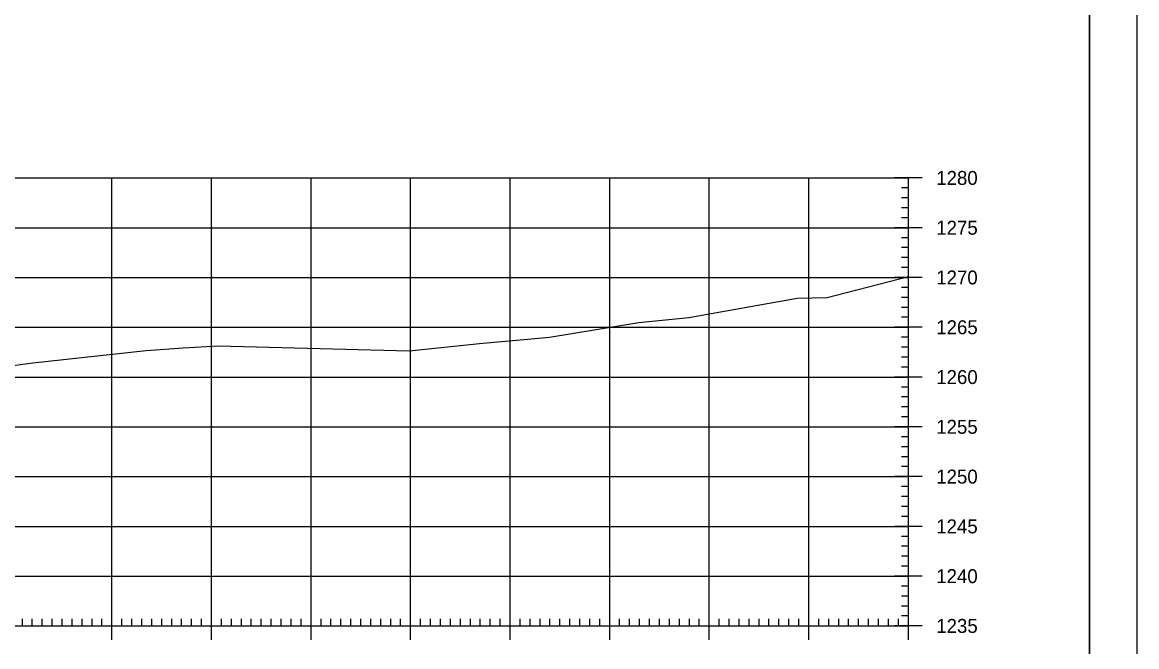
# Model space of a CAD drawing. Extents: x 1406028 to 1412453, y 321733 to 325986.
# Drawn here: x 1409105.8 to 1409217.7, y 322357.5 to 322420.2 of the extents above; entities that cross this region are included whole.
import ezdxf

# ---------------------------------------------------------------- set-up
doc = ezdxf.new("R2010")
doc.units = 0
for name, color, linetype in [('R_Axis', 7, 'Continuous'), ('R_Axis Annot', 7, 'Continuous'), ('R_Border', 7, 'Continuous'), ('R_Exist Surface', 7, 'Continuous'), ('R_Grid', 7, 'Continuous'), ('R_No Plot', 7, 'Continuous')]:
    doc.layers.add(name, color=color, linetype=linetype)

msp = doc.modelspace()

# ---------------------------------------------------------------- linework, layer by layer
at = {"layer": 'R_Axis'}
for p, q in [((1409196.21, 322404.55), (1409193.41, 322404.55)), ((1409194.81, 322359.55), (1409194.81, 322404.55)), ((1409194.81, 322403.55), (1409194.11, 322403.55)), ((1409194.81, 322402.55), (1409194.11, 322402.55)), ((1409194.81, 322401.55), (1409194.11, 322401.55)), ((1409194.81, 322400.55), (1409194.11, 322400.55)), ((1409196.21, 322399.55), (1409193.41, 322399.55)), ((1409194.81, 322398.55), (1409194.11, 322398.55)), ((1409194.81, 322397.55), (1409194.11, 322397.55)), ((1409194.81, 322396.55), (1409194.11, 322396.55)), ((1409194.81, 322395.55), (1409194.11, 322395.55)), ((1409196.21, 322394.55), (1409193.41, 322394.55)), ((1409194.81, 322393.55), (1409194.11, 322393.55)), ((1409194.81, 322392.55), (1409194.11, 322392.55)), ((1409194.81, 322391.55), (1409194.11, 322391.55)), ((1409194.81, 322390.55), (1409194.11, 322390.55)), ((1409196.21, 322389.55), (1409193.41, 322389.55)), ((1409194.81, 322388.55), (1409194.11, 322388.55)), ((1409194.81, 322387.55), (1409194.11, 322387.55)), ((1409194.81, 322386.55), (1409194.11, 322386.55)), ((1409194.81, 322385.55), (1409194.11, 322385.55)), ((1409196.21, 322384.55), (1409193.41, 322384.55)), ((1409194.81, 322383.55), (1409194.11, 322383.55)), ((1409194.81, 322382.55), (1409194.11, 322382.55)), ((1409194.81, 322381.55), (1409194.11, 322381.55)), ((1409194.81, 322380.55), (1409194.11, 322380.55)), ((1409196.21, 322379.55), (1409193.41, 322379.55)), ((1409194.81, 322378.55), (1409194.11, 322378.55)), ((1409194.81, 322377.55), (1409194.11, 322377.55)), ((1409194.81, 322376.55), (1409194.11, 322376.55)), ((1409194.81, 322375.55), (1409194.11, 322375.55)), ((1409196.21, 322374.55), (1409193.41, 322374.55)), ((1409194.81, 322373.55), (1409194.11, 322373.55)), ((1409194.81, 322372.55), (1409194.11, 322372.55)), ((1409194.81, 322371.55), (1409194.11, 322371.55)), ((1409194.81, 322370.55), (1409194.11, 322370.55)), ((1409196.21, 322369.55), (1409193.41, 322369.55)), ((1409194.81, 322368.55), (1409194.11, 322368.55)), ((1409194.81, 322367.55), (1409194.11, 322367.55)), ((1409194.81, 322366.55), (1409194.11, 322366.55)), ((1409194.81, 322365.55), (1409194.11, 322365.55)), ((1409196.21, 322364.55), (1409193.41, 322364.55)), ((1409194.81, 322363.55), (1409194.11, 322363.55)), ((1409194.81, 322362.55), (1409194.11, 322362.55)), ((1409114.81, 322358.15), (1409114.81, 322360.95)), ((1409124.81, 322358.15), (1409124.81, 322360.95)), ((1409134.81, 322358.15), (1409134.81, 322360.95)), ((1409144.81, 322358.15), (1409144.81, 322360.95)), ((1409154.81, 322358.15), (1409154.81, 322360.95)), ((1409164.81, 322358.15), (1409164.81, 322360.95)), ((1409174.81, 322358.15), (1409174.81, 322360.95)), ((1409184.81, 322358.15), (1409184.81, 322360.95)), ((1409194.81, 322361.55), (1409194.11, 322361.55)), ((1409194.81, 322358.15), (1409194.81, 322360.95)), ((1408914.81, 322359.55), (1409194.81, 322359.55)), ((1409105.81, 322359.55), (1409105.81, 322360.25)), ((1409106.81, 322359.55), (1409106.81, 322360.25)), ((1409107.81, 322359.55), (1409107.81, 322360.25)), ((1409108.81, 322359.55), (1409108.81, 322360.25)), ((1409109.81, 322359.55), (1409109.81, 322360.25)), ((1409110.81, 322359.55), (1409110.81, 322360.25)), ((1409111.81, 322359.55), (1409111.81, 322360.25)), ((1409112.81, 322359.55), (1409112.81, 322360.25)), ((1409113.81, 322359.55), (1409113.81, 322360.25)), ((1409115.81, 322359.55), (1409115.81, 322360.25)), ((1409116.81, 322359.55), (1409116.81, 322360.25)), ((1409117.81, 322359.55), (1409117.81, 322360.25)), ((1409118.81, 322359.55), (1409118.81, 322360.25)), ((1409119.81, 322359.55), (1409119.81, 322360.25)), ((1409120.81, 322359.55), (1409120.81, 322360.25)), ((1409121.81, 322359.55), (1409121.81, 322360.25)), ((1409122.81, 322359.55), (1409122.81, 322360.25)), ((1409123.81, 322359.55), (1409123.81, 322360.25)), ((1409125.81, 322359.55), (1409125.81, 322360.25)), ((1409126.81, 322359.55), (1409126.81, 322360.25)), ((1409127.81, 322359.55), (1409127.81, 322360.25)), ((1409128.81, 322359.55), (1409128.81, 322360.25)), ((1409129.81, 322359.55), (1409129.81, 322360.25)), ((1409130.81, 322359.55), (1409130.81, 322360.25)), ((1409131.81, 322359.55), (1409131.81, 322360.25)), ((1409132.81, 322359.55), (1409132.81, 322360.25)), ((1409133.81, 322359.55), (1409133.81, 322360.25)), ((1409135.81, 322359.55), (1409135.81, 322360.25)), ((1409136.81, 322359.55), (1409136.81, 322360.25)), ((1409137.81, 322359.55), (1409137.81, 322360.25)), ((1409138.81, 322359.55), (1409138.81, 322360.25)), ((1409139.81, 322359.55), (1409139.81, 322360.25)), ((1409140.81, 322359.55), (1409140.81, 322360.25)), ((1409141.81, 322359.55), (1409141.81, 322360.25)), ((1409142.81, 322359.55), (1409142.81, 322360.25)), ((1409143.81, 322359.55), (1409143.81, 322360.25)), ((1409145.81, 322359.55), (1409145.81, 322360.25)), ((1409146.81, 322359.55), (1409146.81, 322360.25)), ((1409147.81, 322359.55), (1409147.81, 322360.25)), ((1409148.81, 322359.55), (1409148.81, 322360.25)), ((1409149.81, 322359.55), (1409149.81, 322360.25)), ((1409150.81, 322359.55), (1409150.81, 322360.25)), ((1409151.81, 322359.55), (1409151.81, 322360.25)), ((1409152.81, 322359.55), (1409152.81, 322360.25)), ((1409153.81, 322359.55), (1409153.81, 322360.25)), ((1409155.81, 322359.55), (1409155.81, 322360.25)), ((1409156.81, 322359.55), (1409156.81, 322360.25)), ((1409157.81, 322359.55), (1409157.81, 322360.25)), ((1409158.81, 322359.55), (1409158.81, 322360.25)), ((1409159.81, 322359.55), (1409159.81, 322360.25)), ((1409160.81, 322359.55), (1409160.81, 322360.25)), ((1409161.81, 322359.55), (1409161.81, 322360.25)), ((1409162.81, 322359.55), (1409162.81, 322360.25)), ((1409163.81, 322359.55), (1409163.81, 322360.25)), ((1409165.81, 322359.55), (1409165.81, 322360.25)), ((1409166.81, 322359.55), (1409166.81, 322360.25)), ((1409167.81, 322359.55), (1409167.81, 322360.25)), ((1409168.81, 322359.55), (1409168.81, 322360.25)), ((1409169.81, 322359.55), (1409169.81, 322360.25)), ((1409170.81, 322359.55), (1409170.81, 322360.25)), ((1409171.81, 322359.55), (1409171.81, 322360.25)), ((1409172.81, 322359.55), (1409172.81, 322360.25)), ((1409173.81, 322359.55), (1409173.81, 322360.25)), ((1409175.81, 322359.55), (1409175.81, 322360.25)), ((1409176.81, 322359.55), (1409176.81, 322360.25)), ((1409177.81, 322359.55), (1409177.81, 322360.25)), ((1409178.81, 322359.55), (1409178.81, 322360.25)), ((1409179.81, 322359.55), (1409179.81, 322360.25)), ((1409180.81, 322359.55), (1409180.81, 322360.25)), ((1409181.81, 322359.55), (1409181.81, 322360.25)), ((1409182.81, 322359.55), (1409182.81, 322360.25)), ((1409183.81, 322359.55), (1409183.81, 322360.25)), ((1409185.81, 322359.55), (1409185.81, 322360.25)), ((1409186.81, 322359.55), (1409186.81, 322360.25)), ((1409187.81, 322359.55), (1409187.81, 322360.25)), ((1409188.81, 322359.55), (1409188.81, 322360.25)), ((1409189.81, 322359.55), (1409189.81, 322360.25)), ((1409190.81, 322359.55), (1409190.81, 322360.25)), ((1409191.81, 322359.55), (1409191.81, 322360.25)), ((1409192.81, 322359.55), (1409192.81, 322360.25)), ((1409196.21, 322359.55), (1409193.41, 322359.55)), ((1409193.81, 322359.55), (1409193.81, 322360.25)), ((1409194.81, 322360.55), (1409194.11, 322360.55))]:
    msp.add_line(p, q, dxfattribs=at)
at = {"layer": 'R_Border'}
msp.add_line((1409212.99, 322273.55), (1409212.99, 322479.01), dxfattribs=at)
at = {"layer": 'R_Exist Surface'}
msp.add_lwpolyline([(1409102.38, 322385.37), (1409106.87, 322385.98), (1409118.24, 322387.23), (1409121.95, 322387.48), (1409125.48, 322387.7), (1409144.66, 322387.17), (1409151.72, 322387.92), (1409158.76, 322388.56), (1409167.72, 322390.04), (1409172.77, 322390.53), (1409183.63, 322392.47), (1409186.67, 322392.55), (1409194.81, 322394.65)], dxfattribs=at)
at = {"layer": 'R_Grid'}
for p, q in [((1408914.81, 322404.55), (1409194.81, 322404.55)), ((1409114.81, 322359.55), (1409114.81, 322404.55)), ((1409124.81, 322359.55), (1409124.81, 322404.55)), ((1409134.81, 322359.55), (1409134.81, 322404.55)), ((1409144.81, 322359.55), (1409144.81, 322404.55)), ((1409154.81, 322359.55), (1409154.81, 322404.55)), ((1409164.81, 322359.55), (1409164.81, 322404.55)), ((1409174.81, 322359.55), (1409174.81, 322404.55)), ((1409184.81, 322359.55), (1409184.81, 322404.55)), ((1409194.81, 322359.55), (1409194.81, 322404.55)), ((1408914.81, 322399.55), (1409194.81, 322399.55)), ((1408914.81, 322394.55), (1409194.81, 322394.55)), ((1408914.81, 322389.55), (1409194.81, 322389.55)), ((1408914.81, 322384.55), (1409194.81, 322384.55)), ((1408914.81, 322379.55), (1409194.81, 322379.55)), ((1408914.81, 322374.55), (1409194.81, 322374.55)), ((1408914.81, 322369.55), (1409194.81, 322369.55)), ((1408914.81, 322364.55), (1409194.81, 322364.55)), ((1408914.81, 322359.55), (1409194.81, 322359.55))]:
    msp.add_line(p, q, dxfattribs=at)
at = {"layer": 'R_No Plot'}
for points in [[(1408884.41, 322482.91), (1409217.75, 322482.91), (1409217.75, 322269.57), (1408884.41, 322269.57)], [(1409130.73, 322479.01), (1409150.35, 322479.01), (1409150.35, 322469.13), (1409166.47, 322469.13), (1409189.67, 322469.13), (1409189.67, 322444.8), (1409212.99, 322444.8), (1409212.99, 322273.55), (1408896.81, 322273.55), (1408896.81, 322479.01)]]:
    msp.add_lwpolyline(points, close=True, dxfattribs=at)

# ---------------------------------------------------------------- texts
at = {"layer": 'R_Axis Annot'}
for s, p in [('1280', (1409197.61, 322403.85)), ('1275', (1409197.61, 322398.85)), ('1270', (1409197.61, 322393.85)), ('1265', (1409197.61, 322388.85)), ('1260', (1409197.61, 322383.85)), ('1255', (1409197.61, 322378.85)), ('1250', (1409197.61, 322373.85)), ('1245', (1409197.61, 322368.85)), ('1240', (1409197.61, 322363.85)), ('1235', (1409197.61, 322358.85))]:
    msp.add_text(s, height=1.4, dxfattribs=at).set_placement(p)

doc.saveas('drawing.dxf')
